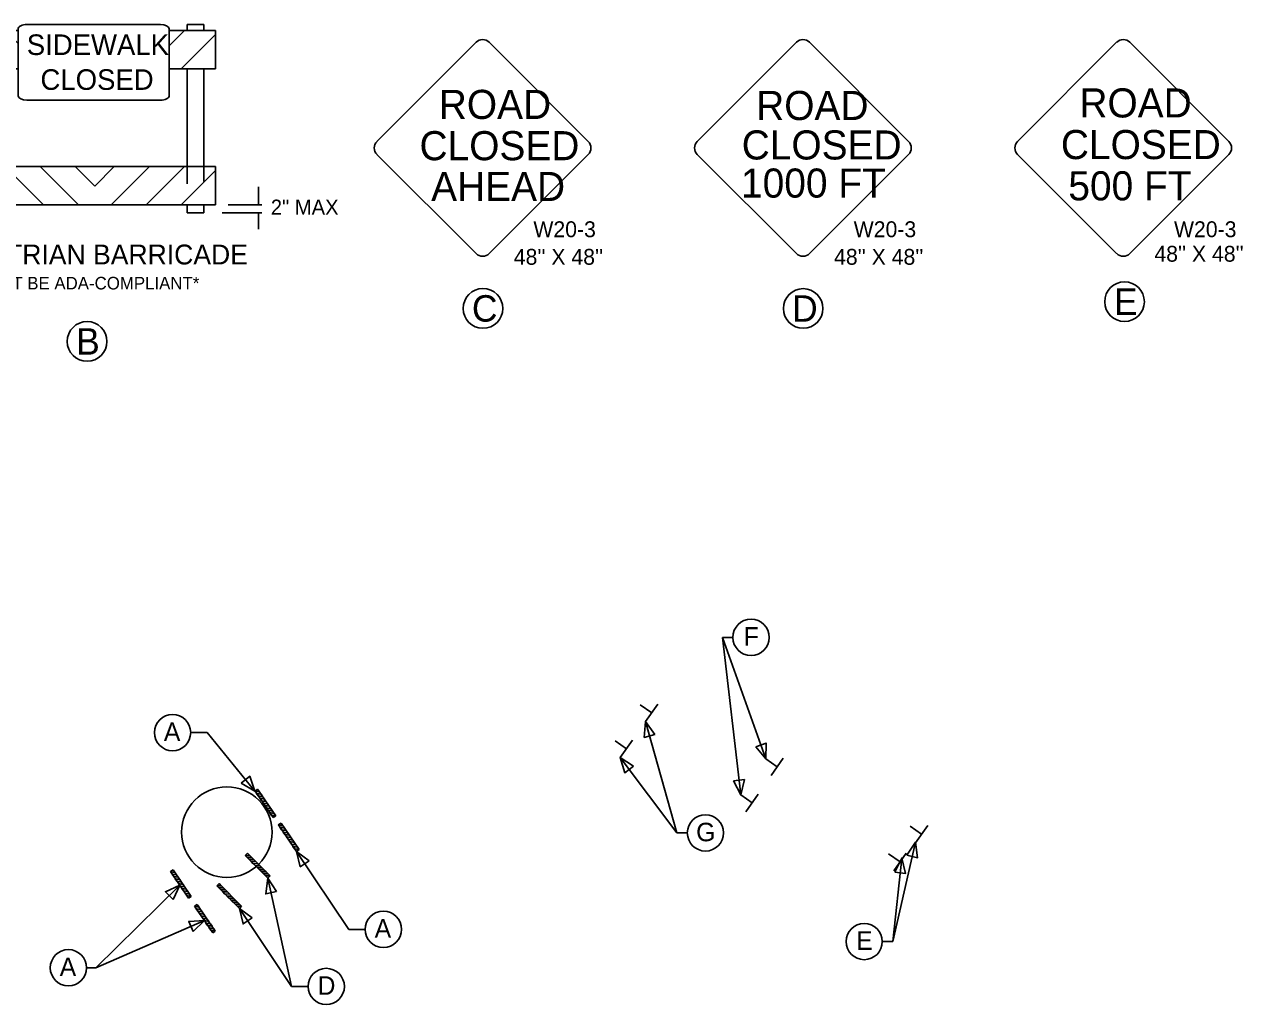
# Model space of a CAD drawing. Extents: x 2157572 to 5059327, y 715220 to 1674494.
# Drawn here: x 2163528 to 2168137, y 715220 to 718927 of the extents above; entities that cross this region are included whole.
import ezdxf

# ---------------------------------------------------------------- set-up
doc = ezdxf.new("R2010")
doc.units = 0
for name, color, linetype in [('Exist Cultural Church Label', 7, 'Continuous'), ('Exist Hydrographic Creek Single Shore Label', 7, 'Continuous'), ('Exist Road Primary US Structure Standard Bridge Number Label', 7, 'Continuous'), ('Exist Road Secondary Type 41 SR Number Label', 7, 'Continuous'), ('Level 51', 7, 'Continuous'), ('Map Preparation County Base Legend Geodetic Marker', 7, 'Continuous'), ('Map Preparation County Base Legend Hangar on Field', 7, 'Continuous'), ('Map Preparation County Base Legend Highway Garage or Maintenance Office', 7, 'Continuous'), ('Map Preparation County Base Legend Marked Auxillary Field', 7, 'Continuous'), ('Map Preparation County Base Legend Military Airfield', 7, 'Continuous'), ('Map Preparation County Base Legend Municipal Field', 7, 'Continuous'), ('Map Preparation County Base Legend Rest Area', 7, 'Continuous'), ('Map Preparation County North Arrow Shadow', 7, 'Continuous')]:
    doc.layers.add(name, color=color, linetype=linetype)

# ---------------------------------------------------------------- blocks, each defined once
blk = doc.blocks.new('PEDBARRSWCLOSED')
at = {"layer": 'Map Preparation County Base Legend Hangar on Field'}
for p, q in [((26.5, 0), (0, 0)), ((0, 0), (-26.5, 0))]:
    blk.add_line(p, q, dxfattribs=at)
for points in [[(-26.5, 30), (0, 30)], [(0, 30), (26.5, 30)], [(-30, 1.75), (-30, 28.25)], [(30, 28.25), (30, 1.75)]]:
    blk.add_lwpolyline(points, dxfattribs=at)
for centre, major_axis, start_param, end_param in [((-26.5, 28.25), (-3.5, 0), 4.712162, 6.283185), ((26.5, 28.25), (3.5, 0), 0, 1.570796), ((-26.5, 1.75), (-3.5, 0), 0, 1.570796), ((26.5, 1.75), (-3.5, 0), 1.570796, 3.141593)]:
    blk.add_ellipse(centre, major_axis=major_axis, ratio=0.5, start_param=start_param, end_param=end_param, dxfattribs=at)
at = {"layer": 'Map Preparation County Base Legend Marked Auxillary Field'}
for p, q in [((-37.19, 30), (-43.76, 30)), ((-43.76, 27.64), (-43.76, 30)), ((-37.19, 27.64), (-37.19, 30)), ((43.76, 30), (37.19, 30)), ((37.19, 27.64), (37.19, 30)), ((43.76, 27.64), (43.76, 30.06)), ((-48.36, 27.64), (-48.36, 12.46)), ((-30, 27.64), (-48.36, 27.64)), ((-35.14, 27.64), (-48.36, 27.64)), ((-30, 22.5), (-35.14, 27.64)), ((30, 21.58), (36.06, 27.64)), ((48.36, 27.64), (30, 27.64)), ((36.06, 27.64), (48.36, 27.64)), ((48.36, 12.46), (48.36, 27.64)), ((-47.82, 12.46), (-48.36, 13.01)), ((-48.36, 12.46), (-47.82, 12.46)), ((-48.36, 12.46), (-30, 12.46)), ((-43.76, -14.53), (-43.76, 12.46)), ((-37.19, -14.53), (-37.19, 12.46)), ((30, 12.46), (48.36, 12.46)), ((37.19, -14.53), (37.19, 12.46)), ((43.76, -14.53), (43.76, 12.46)), ((-43.76, -28.8), (-43.76, -14.53)), ((-37.19, -28.7), (-37.19, -14.53)), ((37.19, -33.18), (37.19, -14.53)), ((43.76, -32.25), (43.76, -14.53)), ((-48.36, -26.35), (-48.36, -41.53)), ((48.36, -26.35), (-48.36, -26.35)), ((-35.14, -26.35), (-48.36, -26.35)), ((-19.97, -41.53), (-35.14, -26.35)), ((-6.04, -41.53), (-21.21, -26.35)), ((-21.21, -26.35), (-7.29, -26.35)), ((-7.29, -26.35), (0.46, -34.1)), ((0.46, -34.1), (8.21, -26.35)), ((22.13, -26.35), (6.96, -41.53)), ((8.21, -26.35), (22.13, -26.35)), ((20.89, -41.53), (36.06, -26.35)), ((36.06, -26.35), (48.36, -26.35)), ((48.36, -41.53), (48.36, -26.35)), ((65.44, -34.49), (65.44, -41.53)), ((-47.82, -41.53), (-48.36, -40.98)), ((-48.36, -41.53), (-47.82, -41.53)), ((-48.36, -41.53), (48.36, -41.53)), ((-43.76, -44.81), (-43.76, -41.53)), ((-37.19, -44.81), (-37.19, -41.53)), ((-33.89, -41.53), (-19.97, -41.53)), ((6.96, -41.53), (-6.96, -41.53)), ((34.81, -41.53), (20.89, -41.53)), ((37.19, -44.81), (37.19, -41.53)), ((43.76, -44.81), (43.76, -41.53)), ((53.37, -41.53), (66.83, -41.53)), ((-37.19, -44.81), (-43.76, -44.81)), ((43.76, -44.81), (37.19, -44.81)), ((51.11, -44.81), (66.83, -44.81)), ((65.44, -44.81), (65.44, -51.17))]:
    blk.add_line(p, q, dxfattribs=at)
for points in [[(-48.36, 27.64), (-48.36, 26.93), (-33.89, 12.46)], [(48.36, 27.64), (48.36, 26.01), (34.81, 12.46)], [(-33.89, 12.46), (-30, 12.46), (-30, 22.5)], [(34.81, 12.46), (30, 12.46), (30, 21.58)], [(-48.36, -26.35), (-48.36, -27.06), (-33.89, -41.53)], [(48.36, -26.35), (48.36, -27.98), (34.81, -41.53)]]:
    blk.add_lwpolyline(points, dxfattribs=at)
at = {"layer": 'Map Preparation County Base Legend Hangar on Field'}
for s, p in [('SIDEWALK', (-26.54, 17.9)), ('CLOSED', (-21.11, 4.07))]:
    blk.add_text(s, height=8.172, dxfattribs=at).set_placement(p)
at = {"layer": 'Map Preparation County Base Legend Marked Auxillary Field'}
for s, height, p in [('2" MAX', 6, (70.36, -45.51)), ('PEDESTRIAN BARRICADE', 7.8816, (-70.5, -65.23)), ('*MUST BE ADA-COMPLIANT*', 5, (-49.77, -75.16))]:
    blk.add_text(s, height=height, dxfattribs=at).set_placement(p)

msp = doc.modelspace()

# ---------------------------------------------------------------- linework, layer by layer
at = {"layer": 'Exist Cultural Church Label'}
for centre in [(2166277.1, 716609.1), (2164088.7, 716248.9), (2166104.6, 715869.6), (2164886.2, 715505.1), (2166705.1, 715458.9), (2163694.7, 715359.8), (2164670.2, 715289.1)]:
    msp.add_circle(centre, 68.6, dxfattribs=at)
at = {"layer": 'Exist Road Primary US Structure Standard Bridge Number Label'}
msp.add_circle((2164294.1, 715872.6), 171, dxfattribs=at)
at = {"layer": 'Exist Road Secondary Type 41 SR Number Label'}
for p, q in [((2164400.7, 716027.7), (2164410.7, 716034.5)), ((2164400.8, 716027.8), (2164410.7, 716034.5)), ((2164410.7, 716034.5), (2164417.4, 716024.6)), ((2164410.7, 716034.5), (2164479.1, 715934.2)), ((2164417.4, 716024.6), (2164400.7, 716027.7)), ((2164469.2, 715927.4), (2164400.8, 716027.8)), ((2164406.8, 716018.6), (2164423.6, 716015.6)), ((2164413, 716009.6), (2164406.8, 716018.6)), ((2164429.8, 716006.6), (2164413, 716009.6)), ((2164419.1, 716000.6), (2164435.9, 715997.5)), ((2164425.3, 715991.5), (2164419.1, 716000.6)), ((2164423.6, 716015.6), (2164429.8, 716006.6)), ((2164442.1, 715988.5), (2164425.3, 715991.5)), ((2164435.9, 715997.5), (2164442.1, 715988.5)), ((2164431.4, 715982.5), (2164448.2, 715979.5)), ((2164437.6, 715973.5), (2164431.4, 715982.5)), ((2164454.4, 715970.5), (2164437.6, 715973.5)), ((2164443.7, 715964.5), (2164460.7, 715961.3)), ((2164449.9, 715955.4), (2164443.7, 715964.5)), ((2164448.2, 715979.5), (2164454.4, 715970.5)), ((2164466.8, 715952.2), (2164449.9, 715955.4)), ((2164456.1, 715946.4), (2164473, 715943.2)), ((2164462.2, 715937.4), (2164456.1, 715946.4)), ((2164460.7, 715961.3), (2164466.8, 715952.2)), ((2164473, 715943.2), (2164479.1, 715934.2)), ((2164479.1, 715934.2), (2164462.2, 715937.4)), ((2164479.1, 715934.2), (2164469.2, 715927.4)), ((2164488.9, 715899.9), (2164499, 715906.8)), ((2164505.7, 715896.9), (2164488.9, 715899.9)), ((2164489.1, 715900), (2164499, 715906.8)), ((2164557.5, 715799.7), (2164489.1, 715900)), ((2164499, 715906.8), (2164505.7, 715896.9)), ((2164499, 715906.8), (2164567.4, 715806.4)), ((2164495.1, 715890.9), (2164511.9, 715887.9)), ((2164501.2, 715881.9), (2164495.1, 715890.9)), ((2164518, 715878.8), (2164501.2, 715881.9)), ((2164507.4, 715872.8), (2164524.2, 715869.8)), ((2164513.6, 715863.8), (2164507.4, 715872.8)), ((2164511.9, 715887.9), (2164518, 715878.8)), ((2164530.3, 715860.8), (2164513.6, 715863.8)), ((2164519.7, 715854.8), (2164536.5, 715851.8)), ((2164525.9, 715845.8), (2164519.7, 715854.8)), ((2164524.2, 715869.8), (2164530.3, 715860.8)), ((2164536.5, 715851.8), (2164542.7, 715842.7)), ((2164542.7, 715842.7), (2164525.9, 715845.8)), ((2164532, 715836.7), (2164548.9, 715833.5)), ((2164538.2, 715827.7), (2164532, 715836.7)), ((2164555.1, 715824.5), (2164538.2, 715827.7)), ((2164544.3, 715818.7), (2164561.2, 715815.5)), ((2164550.5, 715809.6), (2164544.3, 715818.7)), ((2164548.9, 715833.5), (2164555.1, 715824.5)), ((2164567.4, 715806.4), (2164550.5, 715809.6)), ((2164567.4, 715806.4), (2164557.5, 715799.7)), ((2164561.2, 715815.5), (2164567.4, 715806.4)), ((2164363.6, 715784.5), (2164372.2, 715793)), ((2164380.6, 715784.5), (2164363.6, 715784.5)), ((2164363.7, 715784.6), (2164372.2, 715793)), ((2164449.2, 715698.4), (2164363.7, 715784.6)), ((2164371.3, 715776.7), (2164388.3, 715776.8)), ((2164379, 715769), (2164371.3, 715776.7)), ((2164372.2, 715793), (2164380.6, 715784.5)), ((2164372.2, 715793), (2164457.7, 715706.8)), ((2164396, 715769), (2164379, 715769)), ((2164386.6, 715761.2), (2164403.7, 715761.3)), ((2164394.3, 715753.4), (2164386.6, 715761.2)), ((2164388.3, 715776.8), (2164396, 715769)), ((2164403.7, 715761.3), (2164411.4, 715753.5)), ((2164080.7, 715723.1), (2164090.8, 715729.9)), ((2164097.5, 715720), (2164080.7, 715723.1)), ((2164080.9, 715723.2), (2164090.8, 715729.9)), ((2164149.3, 715622.9), (2164080.9, 715723.2)), ((2164086.9, 715714), (2164103.7, 715711)), ((2164093, 715705), (2164086.9, 715714)), ((2164090.8, 715729.9), (2164097.5, 715720)), ((2164090.8, 715729.9), (2164159.2, 715629.6)), ((2164103.7, 715711), (2164109.8, 715702)), ((2164411.4, 715753.5), (2164394.3, 715753.4)), ((2164402, 715745.7), (2164419.1, 715745.8)), ((2164409.7, 715737.9), (2164402, 715745.7)), ((2164426.8, 715738), (2164409.7, 715737.9)), ((2164417.4, 715730.2), (2164434.6, 715730.1)), ((2164425.1, 715722.4), (2164417.4, 715730.2)), ((2164419.1, 715745.8), (2164426.8, 715738)), ((2164442.3, 715722.3), (2164425.1, 715722.4)), ((2164432.8, 715714.6), (2164450, 715714.6)), ((2164440.5, 715706.9), (2164432.8, 715714.6)), ((2164434.6, 715730.1), (2164442.3, 715722.3)), ((2164450, 715714.6), (2164457.7, 715706.8)), ((2164109.8, 715702), (2164093, 715705)), ((2164099.2, 715696), (2164116, 715693)), ((2164105.3, 715687), (2164099.2, 715696)), ((2164122.1, 715683.9), (2164105.3, 715687)), ((2164111.5, 715677.9), (2164128.3, 715674.9)), ((2164117.7, 715668.9), (2164111.5, 715677.9)), ((2164116, 715693), (2164122.1, 715683.9)), ((2164134.4, 715665.9), (2164117.7, 715668.9)), ((2164128.3, 715674.9), (2164134.4, 715665.9)), ((2164255.9, 715669.7), (2164264.5, 715678.3)), ((2164272.9, 715669.8), (2164255.9, 715669.7)), ((2164256, 715669.9), (2164264.5, 715678.3)), ((2164341.5, 715583.7), (2164256, 715669.9)), ((2164263.6, 715662), (2164280.6, 715662.1)), ((2164271.3, 715654.2), (2164263.6, 715662)), ((2164264.5, 715678.3), (2164272.9, 715669.8)), ((2164264.5, 715678.3), (2164350, 715592.1)), ((2164280.6, 715662.1), (2164288.3, 715654.3)), ((2164457.7, 715706.8), (2164440.5, 715706.9)), ((2164457.7, 715706.8), (2164449.2, 715698.4)), ((2164123.8, 715659.9), (2164140.7, 715656.7)), ((2164130, 715650.8), (2164123.8, 715659.9)), ((2164146.9, 715647.6), (2164130, 715650.8)), ((2164136.1, 715641.8), (2164153, 715638.6)), ((2164142.3, 715632.8), (2164136.1, 715641.8)), ((2164140.7, 715656.7), (2164146.9, 715647.6)), ((2164159.2, 715629.6), (2164142.3, 715632.8)), ((2164159.2, 715629.6), (2164149.3, 715622.9)), ((2164153, 715638.6), (2164159.2, 715629.6)), ((2164288.3, 715654.3), (2164271.3, 715654.2)), ((2164279, 715646.5), (2164296, 715646.5)), ((2164286.6, 715638.7), (2164279, 715646.5)), ((2164303.7, 715638.8), (2164286.6, 715638.7)), ((2164294.3, 715630.9), (2164311.4, 715631)), ((2164302, 715623.2), (2164294.3, 715630.9)), ((2164296, 715646.5), (2164303.7, 715638.8)), ((2164319.1, 715623.3), (2164302, 715623.2)), ((2164311.4, 715631), (2164319.1, 715623.3)), ((2164172.1, 715592.1), (2164182.1, 715598.9)), ((2164188.9, 715589), (2164172.1, 715592.1)), ((2164172.3, 715592.2), (2164182.1, 715598.9)), ((2164240.7, 715491.8), (2164172.3, 715592.2)), ((2164178.2, 715583), (2164195, 715580)), ((2164184.4, 715574), (2164178.2, 715583)), ((2164182.1, 715598.9), (2164188.9, 715589)), ((2164182.1, 715598.9), (2164250.5, 715498.6)), ((2164201.2, 715571), (2164184.4, 715574)), ((2164195, 715580), (2164201.2, 715571)), ((2164309.7, 715615.4), (2164326.9, 715615.4)), ((2164317.4, 715607.7), (2164309.7, 715615.4)), ((2164334.6, 715607.6), (2164317.4, 715607.7)), ((2164325.1, 715599.9), (2164342.3, 715599.8)), ((2164332.8, 715592.2), (2164325.1, 715599.9)), ((2164326.9, 715615.4), (2164334.6, 715607.6)), ((2164350, 715592.1), (2164332.8, 715592.2)), ((2164350, 715592.1), (2164341.5, 715583.7)), ((2164342.3, 715599.8), (2164350, 715592.1)), ((2164190.5, 715565), (2164207.3, 715561.9)), ((2164196.7, 715555.9), (2164190.5, 715565)), ((2164213.5, 715552.9), (2164196.7, 715555.9)), ((2164202.9, 715546.9), (2164219.6, 715543.9)), ((2164209, 715537.9), (2164202.9, 715546.9)), ((2164207.3, 715561.9), (2164213.5, 715552.9)), ((2164225.8, 715534.9), (2164209, 715537.9)), ((2164215.2, 715528.9), (2164232.1, 715525.7)), ((2164221.3, 715519.8), (2164215.2, 715528.9)), ((2164219.6, 715543.9), (2164225.8, 715534.9)), ((2164232.1, 715525.7), (2164238.2, 715516.6)), ((2164238.2, 715516.6), (2164221.3, 715519.8)), ((2164227.5, 715510.8), (2164244.4, 715507.6)), ((2164233.6, 715501.8), (2164227.5, 715510.8)), ((2164250.5, 715498.6), (2164233.6, 715501.8)), ((2164250.5, 715498.6), (2164240.7, 715491.8)), ((2164244.4, 715507.6), (2164250.5, 715498.6))]:
    msp.add_line(p, q, dxfattribs=at)
at = {"layer": 'Level 51'}
for p, q in [((2166208.4, 716609.1), (2166168.8, 716609.1)), ((2166168.8, 716609.1), (2166238.2, 716013.5)), ((2166168.8, 716609.1), (2166333.1, 716149.7)), ((2165996.4, 715869.6), (2165877.8, 716290.4)), ((2164219.7, 716248.9), (2164157.4, 716248.9)), ((2164219.7, 716248.9), (2164399.9, 716027.1)), ((2165996.4, 715869.6), (2165782.6, 716154.4)), ((2166036, 715869.6), (2165996.4, 715869.6)), ((2166813.4, 715458.9), (2166899.5, 715835.2)), ((2164755.3, 715505.1), (2164557.5, 715799.7)), ((2166813.4, 715458.9), (2166847.2, 715774.5)), ((2163799, 715359.8), (2164116.1, 715671.5)), ((2164539.3, 715289.1), (2164449.2, 715698.4)), ((2164539.3, 715289.1), (2164341.5, 715583.7)), ((2163799, 715359.8), (2164210, 715538.3)), ((2164817.6, 715505.1), (2164755.3, 715505.1)), ((2166813.4, 715458.9), (2166773.8, 715458.9)), ((2163763.3, 715359.8), (2163799, 715359.8)), ((2164601.6, 715289.1), (2164539.3, 715289.1))]:
    msp.add_line(p, q, dxfattribs=at)
for points in [[(2165913, 716242.1), (2165873.1, 716230.9), (2165877.8, 716290.4)], [(2166294.7, 716195.5), (2166333.8, 716209.4), (2166333.1, 716149.7)], [(2165832.8, 716122), (2165799.6, 716097.2), (2165782.6, 716154.4)], [(2164348.5, 716057.6), (2164380.6, 716083.7), (2164399.9, 716027.1)], [(2166211.1, 716066.7), (2166252.3, 716071.5), (2166238.2, 716013.5)], [(2166866.8, 715785.2), (2166907.2, 715776), (2166899.5, 715835.2)], [(2164606, 715764.7), (2164571.5, 715741.6), (2164557.5, 715799.7)], [(2166820.6, 715721), (2166861.8, 715716.6), (2166847.2, 715774.5)], [(2164090.7, 715617.5), (2164061.6, 715647), (2164116.1, 715671.5)], [(2164481.5, 715648.1), (2164441, 715639.2), (2164449.2, 715698.4)], [(2164390, 715548.7), (2164355.5, 715525.6), (2164341.5, 715583.7)], [(2164166.9, 715497), (2164150.3, 715535), (2164210, 715538.3)]]:
    msp.add_lwpolyline(points, close=True, dxfattribs=at)
at = {"layer": 'Map Preparation County Base Legend Geodetic Marker'}
for points in [[(2166073.8, 718484.3), (2166448.6, 718859.1)], [(2166498.1, 718859.1), (2166872.8, 718484.3)], [(2166448.6, 718060), (2166073.8, 718434.8)], [(2166872.8, 718434.8), (2166498.1, 718060)]]:
    msp.add_lwpolyline(points, dxfattribs=at)
for centre, start, end in [((2166473.3, 718834.3), 89.9935, 135), ((2166473.3, 718834.3), 44.987, 89.9935), ((2166098.5, 718459.5), 135, 225), ((2166848.1, 718459.5), 315, 45), ((2166473.3, 718084.8), 225, 270), ((2166473.3, 718084.8), 270, 315)]:
    msp.add_arc(centre, 35, start, end, dxfattribs=at)
at = {"layer": 'Map Preparation County Base Legend Highway Garage or Maintenance Office'}
for centre in [(2166277.1, 716609.1), (2164088.7, 716248.9), (2166104.6, 715869.6), (2164886.2, 715505.1), (2166705.1, 715458.9), (2163694.7, 715359.8), (2164670.2, 715289.1)]:
    msp.add_circle(centre, 68.6, dxfattribs=at)
at = {"layer": 'Map Preparation County Base Legend Military Airfield'}
msp.add_line((2168084.5, 718434.8), (2167709.7, 718060), dxfattribs=at)
for points in [[(2167285.5, 718484.3), (2167660.2, 718859.1)], [(2167709.7, 718859.1), (2168084.5, 718484.3)], [(2167660.2, 718060), (2167285.5, 718434.8)]]:
    msp.add_lwpolyline(points, dxfattribs=at)
for centre, start, end in [((2167685, 718834.3), 89.9935, 135), ((2167685, 718834.3), 44.987, 89.9935), ((2167310.2, 718459.5), 135, 225), ((2168059.7, 718459.5), 315, 45), ((2167685, 718084.8), 225, 270), ((2167685, 718084.8), 270, 315)]:
    msp.add_arc(centre, 35, start, end, dxfattribs=at)
at = {"layer": 'Map Preparation County Base Legend Municipal Field'}
msp.add_line((2165661.1, 718434.8), (2165286.4, 718060), dxfattribs=at)
for points in [[(2164862.1, 718484.3), (2165236.9, 718859.1)], [(2165286.4, 718859.1), (2165661.1, 718484.3)], [(2165236.9, 718060), (2164862.1, 718434.8)]]:
    msp.add_lwpolyline(points, dxfattribs=at)
for centre, start, end in [((2165261.6, 718834.3), 89.9935, 135), ((2165261.6, 718834.3), 44.987, 89.9935), ((2164886.9, 718459.5), 135, 225), ((2165636.4, 718459.5), 315, 45), ((2165261.6, 718084.8), 225, 270), ((2165261.6, 718084.8), 270, 315)]:
    msp.add_arc(centre, 35, start, end, dxfattribs=at)
at = {"layer": 'Map Preparation County Base Legend Rest Area'}
for centre in [(2165263.1, 717852.9), (2166474.3, 717852.6), (2167689.9, 717878.3), (2163765.4, 717728.1)]:
    msp.add_circle(centre, 75, dxfattribs=at)
at = {"layer": 'Map Preparation County North Arrow Shadow'}
for p, q in [((2165901.2, 716323.9), (2165858.1, 716353.9)), ((2165877.8, 716290.4), (2165924.2, 716356.9)), ((2165805.9, 716187.9), (2165762.9, 716217.9)), ((2165782.6, 716154.4), (2165828.9, 716220.9)), ((2166376.2, 716119.7), (2166333.1, 716149.7)), ((2166352.8, 716086.2), (2166399.2, 716152.6)), ((2166281.2, 715983.5), (2166238.2, 716013.5)), ((2166257.9, 715950), (2166304.2, 716016.4)), ((2166922.3, 715865.2), (2166879.2, 715895.2)), ((2166898.9, 715831.7), (2166945.3, 715898.2)), ((2166840.7, 715760.3), (2166797.6, 715790.3)), ((2166817.3, 715726.8), (2166863.6, 715793.3))]:
    msp.add_line(p, q, dxfattribs=at)

# ---------------------------------------------------------------- block references
at = {"layer": 'Exist Hydrographic Creek Single Shore Label', "xscale": 9.525466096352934, "yscale": 9.525466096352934, "rotation": -1.2796055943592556e-10}
msp.add_blockref('PEDBARRSWCLOSED', (2163790.2, 718640.5), dxfattribs=at)

# ---------------------------------------------------------------- texts
at = {"layer": 'Exist Road Primary US Structure Standard Bridge Number Label'}
for s, p in [('F', (2166249.2, 716577.7)), ('A', (2164055.8, 716217.5)), ('G', (2166069.4, 715838.1)), ('A', (2164853.3, 715473.7)), ('E', (2166674.9, 715427.5)), ('A', (2163661.8, 715328.4)), ('D', (2164637.3, 715257.7))]:
    msp.add_text(s, height=70, dxfattribs=at).set_placement(p)
at = {"layer": 'Map Preparation County Base Legend Geodetic Marker'}
for s, height, p in [('ROAD', 110, (2166296.4, 718565.2)), ('CLOSED', 110, (2166241.8, 718416)), ('1000 FT', 110, (2166239.2, 718271.8)), ('W20-3', 60, (2166665.4, 718122.2)), ("48'' X 48''", 60, (2166591.2, 718017.9))]:
    msp.add_text(s, height=height, rotation=360, dxfattribs=at).set_placement(p)
at = {"layer": 'Map Preparation County Base Legend Military Airfield'}
for s, height, p in [('ROAD', 110, (2167519.2, 718574.9)), ('CLOSED', 110, (2167449.2, 718417.4)), ('500 FT', 110, (2167477.3, 718261.4)), ('W20-3', 60, (2167877.1, 718122.2)), ("48'' X 48''", 60, (2167802.9, 718029.5))]:
    msp.add_text(s, height=height, rotation=360, dxfattribs=at).set_placement(p)
at = {"layer": 'Map Preparation County Base Legend Municipal Field'}
for s, height, p in [('ROAD', 110, (2165095.8, 718569.3)), ('CLOSED', 110, (2165022.9, 718413.2)), ('AHEAD', 110, (2165066.9, 718259)), ('W20-3', 60, (2165453.7, 718122.2)), ("48'' X 48''", 60, (2165379.6, 718017.9))]:
    msp.add_text(s, height=height, rotation=360, dxfattribs=at).set_placement(p)
at = {"layer": 'Map Preparation County Base Legend Rest Area'}
for s, p in [('E', (2167650.2, 717828.3)), ('C', (2165221.3, 717802.9)), ('D', (2166432.6, 717802.6)), ('B', (2163724.2, 717678.1))]:
    msp.add_text(s, height=100, rotation=360, dxfattribs=at).set_placement(p)

doc.saveas('drawing.dxf')
